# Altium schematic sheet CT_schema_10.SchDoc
size 226 x 144 mm
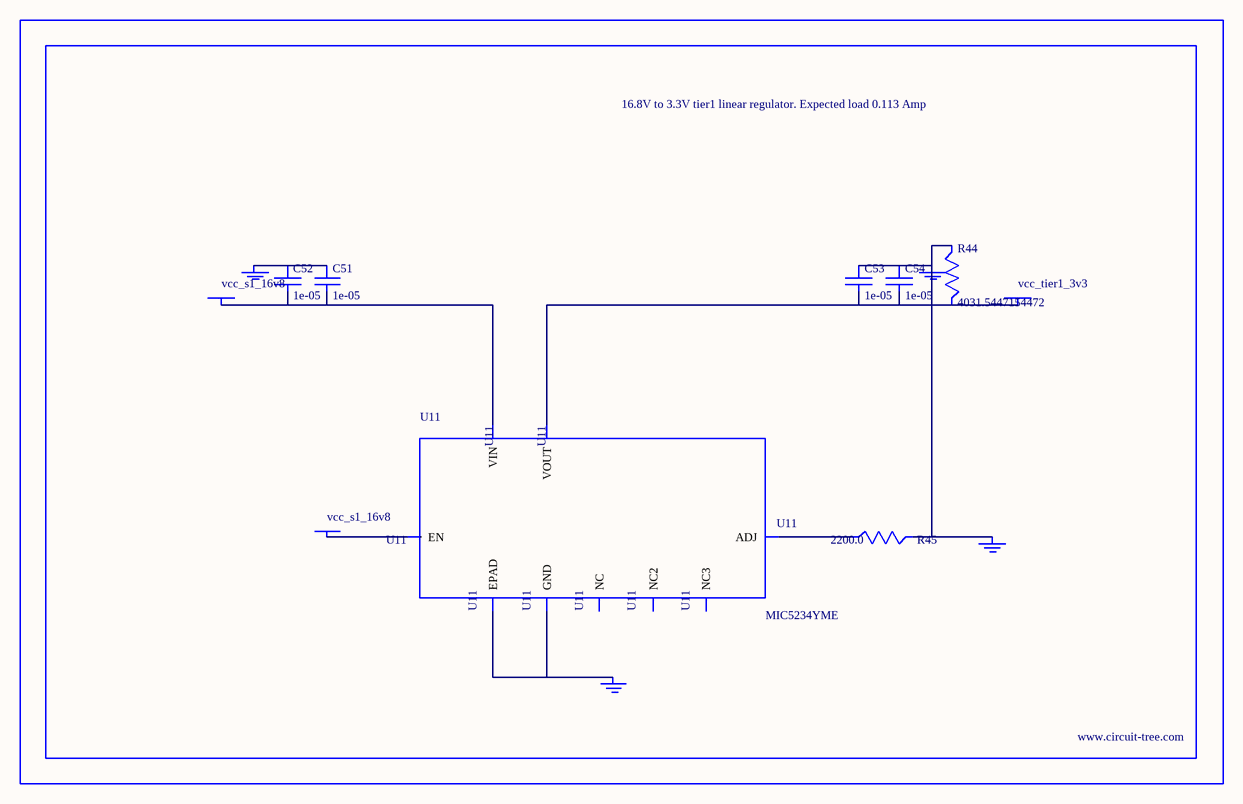
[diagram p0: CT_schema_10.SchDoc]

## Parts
BORDER9  (no value)
C51  1e-05  [C1210]
C52  1e-05  [C1210]
C53  1e-05  [C1210]
C54  1e-05  [C1210]
GND_INSTANCE_9_0  (no value)
GND_INSTANCE_9_1  (no value)
GND_INSTANCE_9_2  (no value)
GND_INSTANCE_9_3  (no value)
POWER_INSTANCE_9_0  vcc_tier1_3v3
POWER_INSTANCE_9_1  vcc_s1_16v8
POWER_INSTANCE_9_2  vcc_s1_16v8
R44  4031.5447154472  [R0603]
R45  2200.0  [R0603]
U11  MIC5234YME  [SOIC-8_EP]

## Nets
NetC51_1: C51.1 C52.1 GND_INSTANCE_9_3.0(GND)
NetC51_2: C51.2 C52.2 POWER_INSTANCE_9_2.0(PWR) U11.8(VIN)
NetC53_1: C53.1 C54.1 GND_INSTANCE_9_0.0(GND) GND_INSTANCE_9_1.0(GND) R44.1 R45.2
NetC53_2: C53.2 C54.2 POWER_INSTANCE_9_0.0(PWR) R44.2 U11.1(VOUT)
NetGND_INSTANCE_9_2_0: GND_INSTANCE_9_2.0(GND) U11.7(GND) U11.EPAD
NetPOWER_INSTANCE_9_1_0: POWER_INSTANCE_9_1.0(PWR) U11.5(EN)
NetR45_1: R45.1 U11.4(ADJ)

Not connected (* = marked no-connect by the designer): U11 2(NC) 3(NC2) 6(NC3)

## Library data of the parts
BORDER9 = BORDER_PAGE9
C51-C54 = C1210C106K5PACTU
GND_INSTANCE_9_0-GND_INSTANCE_9_3 = GND
POWER_INSTANCE_9_0-POWER_INSTANCE_9_2 = PWR
R44 = R44
R45 = RC0603JR-072K2L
